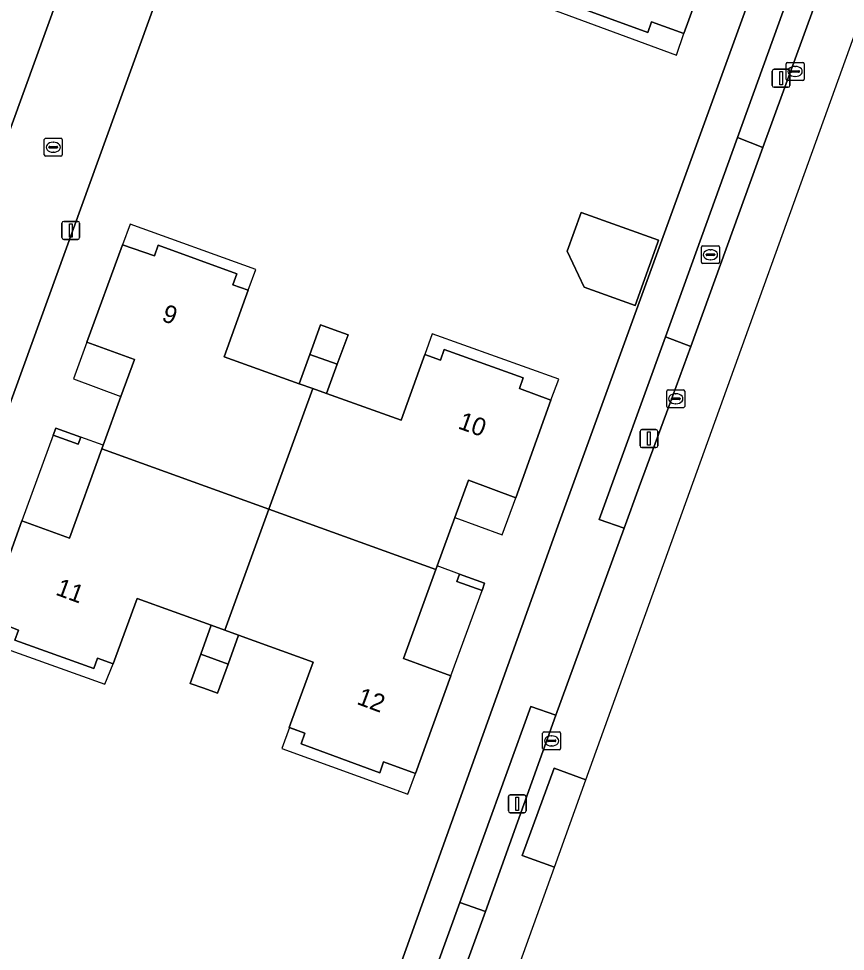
# Model space of a CAD drawing. Extents: x 155887 to 156869, y 383880 to 384678.
# Drawn here: x 156722.6 to 156768.8, y 384103.4 to 384155.6 of the extents above; entities that cross this region are included whole.
import ezdxf

# ---------------------------------------------------------------- set-up
doc = ezdxf.new("R2010")
doc.units = 0
for name, color, linetype in [('IMGEO_Erf', 7, 'Continuous'), ('IMGEO_Groenvoorziening', 7, 'Continuous'), ('IMGEO_Haag', 7, 'Continuous'), ('IMGEO_Kolk', 7, 'Continuous'), ('IMGEO_Lichtmast', 7, 'Continuous'), ('IMGEO_Pand', 7, 'Continuous'), ('IMGEO_Pand_nummerreeks', 7, 'Continuous'), ('IMGEO_Pand_overbouw', 7, 'Continuous'), ('IMGEO_Parkeervlak_open', 7, 'Continuous'), ('IMGEO_Rijbaan_lokaal_open', 7, 'Continuous'), ('IMGEO_Rioolput', 7, 'Continuous'), ('IMGEO_Voetpad_open', 7, 'Continuous')]:
    doc.layers.add(name, color=color, linetype=linetype)

msp = doc.modelspace()

# ---------------------------------------------------------------- linework, layer by layer
at = {"layer": 'IMGEO_Erf'}
for points in [[(156785.484, 384217.152), (156762.028, 384244.15), (156702.835, 384080.846), (156718.715, 384062.632)], [(156721.885, 384060.186), (156727.592, 384057.564), (156727.82, 384058.123), (156737.823, 384085.568), (156752.766, 384127.202), (156785.484, 384217.152)], [(156761.79, 384160.158), (156759.82, 384154.742), (156758.015, 384155.397), (156757.795, 384154.796), (156753.397, 384156.4)], [(156720.836, 384122.088), (156722.808, 384127.499), (156725.468, 384126.532), (156727.276, 384131.53), (156727.35, 384131.732), (156728.335, 384134.455), (156729.101, 384136.516), (156726.442, 384137.485), (156728.431, 384142.937), (156730.211, 384142.316), (156730.422, 384142.92), (156734.829, 384141.306), (156734.606, 384140.703), (156735.466, 384140.393), (156735.315, 384139.98), (156734.11, 384136.666), (156738.31, 384135.166), (156738.909, 384136.809), (156739.507, 384138.452), (156740.273, 384138.173), (156741.039, 384137.894), (156740.442, 384136.256), (156739.845, 384134.617), (156744.007, 384133.13), (156745.19, 384136.382), (156745.34, 384136.795), (156746.202, 384136.482), (156746.419, 384137.085), (156750.835, 384135.494), (156750.627, 384134.906), (156752.388, 384134.248), (156750.414, 384128.79), (156747.777, 384129.785), (156747.014, 384127.69), (156746.028, 384124.979), (156745.953, 384124.773), (156744.143, 384119.801), (156746.794, 384118.839), (156744.812, 384113.379), (156743.031, 384114.026), (156742.811, 384113.425), (156738.413, 384115.029), (156738.632, 384115.631), (156737.753, 384115.947), (156737.903, 384116.361), (156739.1, 384119.607), (156734.925, 384121.117), (156734.337, 384119.49), (156733.748, 384117.863), (156732.974, 384118.143), (156732.216, 384118.417), (156732.804, 384120.044), (156733.392, 384121.671), (156729.25, 384123.169), (156728.055, 384119.922), (156727.903, 384119.509), (156727.032, 384119.83), (156726.819, 384119.241), (156722.402, 384120.826)]]:
    msp.add_lwpolyline(points, dxfattribs=at)
for points in [[(156748.746, 384222.717), (156729.008, 384230.275), (156713.159, 384216.382), (156675.458, 384112.297), (156698.866, 384085.52), (156698.981, 384085.572)], [(156754.076, 384144.739), (156758.404, 384143.188), (156758.346, 384143.027), (156757.096, 384139.538), (156754.242, 384140.56), (156753.298, 384142.568)], [(156726.098, 384132.185), (156725.951, 384131.781), (156724.55, 384132.288), (156724.697, 384132.692)], [(156747.278, 384124.522), (156748.679, 384124.015), (156748.532, 384123.611), (156747.132, 384124.117)]]:
    msp.add_lwpolyline(points, close=True, dxfattribs=at)
at = {"layer": 'IMGEO_Groenvoorziening'}
for points in [[(156767.708, 384157.902), (156766.253, 384158.427), (156762.823, 384148.938), (156764.239, 384148.375)], [(156758.97, 384133.889), (156760.201, 384137.255), (156758.784, 384137.787), (156755.082, 384127.579), (156756.483, 384127.088), (156757.328, 384129.399)], [(156752.663, 384116.638), (156751.259, 384117.124), (156747.294, 384106.163), (156748.733, 384105.664)]]:
    msp.add_lwpolyline(points, close=True, dxfattribs=at)
at = {"layer": 'IMGEO_Haag'}
for points in [[(156764.239, 384148.375), (156767.708, 384157.902), (156766.253, 384158.427), (156762.823, 384148.938)], [(156757.328, 384129.399), (156758.97, 384133.889), (156760.201, 384137.255), (156758.784, 384137.787), (156755.082, 384127.579), (156756.483, 384127.088)], [(156748.733, 384105.664), (156752.663, 384116.638), (156751.259, 384117.124), (156747.294, 384106.163)]]:
    msp.add_lwpolyline(points, close=True, dxfattribs=at)
at = {"layer": 'IMGEO_Kolk'}
for p, q in [((156765.539, 384152.197), (156765.539, 384153.049)), ((156765.614, 384153.123), (156766.466, 384153.123)), ((156765.798, 384152.617), (156765.798, 384152.629)), ((156765.841, 384152.666), (156766.239, 384152.666)), ((156766.027, 384152.903), (156766.052, 384152.903)), ((156766.282, 384152.629), (156766.282, 384152.617)), ((156766.54, 384153.049), (156766.54, 384152.197)), ((156766.466, 384152.123), (156765.614, 384152.123)), ((156766.236, 384152.58), (156765.838, 384152.58)), ((156766.05, 384152.343), (156766.025, 384152.343)), ((156724.059, 384147.96), (156724.059, 384148.812)), ((156724.134, 384148.886), (156724.986, 384148.886)), ((156724.547, 384148.666), (156724.572, 384148.666)), ((156725.06, 384148.812), (156725.06, 384147.96)), ((156724.318, 384148.38), (156724.318, 384148.392)), ((156724.756, 384148.343), (156724.358, 384148.343)), ((156724.361, 384148.429), (156724.759, 384148.429)), ((156724.57, 384148.106), (156724.545, 384148.106)), ((156724.802, 384148.392), (156724.802, 384148.38)), ((156724.986, 384147.886), (156724.134, 384147.886)), ((156758.865, 384133.901), (156758.865, 384134.753)), ((156758.94, 384134.827), (156759.792, 384134.827)), ((156759.353, 384134.607), (156759.378, 384134.607)), ((156759.866, 384134.753), (156759.866, 384133.901)), ((156759.124, 384134.321), (156759.124, 384134.333)), ((156759.562, 384134.284), (156759.164, 384134.284)), ((156759.167, 384134.37), (156759.565, 384134.37)), ((156759.376, 384134.047), (156759.351, 384134.047)), ((156759.608, 384134.333), (156759.608, 384134.321)), ((156759.792, 384133.827), (156758.94, 384133.827)), ((156751.923, 384114.778), (156751.923, 384115.63)), ((156751.998, 384115.704), (156752.85, 384115.704)), ((156752.924, 384115.63), (156752.924, 384114.778)), ((156752.182, 384115.198), (156752.182, 384115.21)), ((156752.62, 384115.161), (156752.222, 384115.161)), ((156752.225, 384115.247), (156752.623, 384115.247)), ((156752.411, 384115.484), (156752.436, 384115.484)), ((156752.666, 384115.21), (156752.666, 384115.198)), ((156752.85, 384114.704), (156751.998, 384114.704)), ((156752.434, 384114.924), (156752.409, 384114.924))]:
    msp.add_line(p, q, dxfattribs=at)
for points in [[(156765.539, 384152.197), (156765.539, 384153.049)], [(156765.614, 384153.123), (156766.466, 384153.123)], [(156766.54, 384153.049), (156766.54, 384152.197)], [(156766.466, 384152.123), (156765.614, 384152.123)], [(156724.059, 384147.96), (156724.059, 384148.812)], [(156724.134, 384148.886), (156724.986, 384148.886)], [(156725.06, 384148.812), (156725.06, 384147.96)], [(156724.986, 384147.886), (156724.134, 384147.886)], [(156758.865, 384133.901), (156758.865, 384134.753)], [(156758.94, 384134.827), (156759.792, 384134.827)], [(156759.866, 384134.753), (156759.866, 384133.901)], [(156759.792, 384133.827), (156758.94, 384133.827)], [(156751.923, 384114.778), (156751.923, 384115.63)], [(156751.998, 384115.704), (156752.85, 384115.704)], [(156752.924, 384115.63), (156752.924, 384114.778)], [(156752.85, 384114.704), (156751.998, 384114.704)]]:
    msp.add_lwpolyline(points, dxfattribs=at)
for centre, radius, start, end in [((156765.616, 384153.047), 0.0765, 91.552, 178.448), ((156765.616, 384153.047), 0.0765, 91.552, 178.448), ((156765.838, 384152.626), 0.0403, 85.8775, 175.7526), ((156766.243, 384152.628), 0.0386, 1.7309, 96.639), ((156766.464, 384153.047), 0.0765, 1.552, 88.448), ((156766.464, 384153.047), 0.0765, 1.552, 88.448), ((156765.616, 384152.199), 0.0765, 181.552, 268.448), ((156765.616, 384152.199), 0.0765, 181.552, 268.448), ((156765.835, 384152.616), 0.0366, 178.938, 274.7102), ((156766.239, 384152.623), 0.043, 264.8664, 352.4533), ((156766.464, 384152.199), 0.0765, 271.552, 358.448), ((156766.464, 384152.199), 0.0765, 271.552, 358.448), ((156724.136, 384148.81), 0.0765, 91.552, 178.448), ((156724.136, 384148.81), 0.0765, 91.552, 178.448), ((156724.984, 384148.81), 0.0765, 1.552, 88.448), ((156724.984, 384148.81), 0.0765, 1.552, 88.448), ((156724.136, 384147.962), 0.0765, 181.552, 268.448), ((156724.136, 384147.962), 0.0765, 181.552, 268.448), ((156724.358, 384148.389), 0.0403, 85.8775, 175.7526), ((156724.355, 384148.379), 0.0366, 178.938, 274.7102), ((156724.759, 384148.386), 0.043, 264.8664, 352.4533), ((156724.763, 384148.391), 0.0386, 1.7309, 96.639), ((156724.984, 384147.962), 0.0765, 271.552, 358.448), ((156724.984, 384147.962), 0.0765, 271.552, 358.448), ((156758.942, 384134.751), 0.0765, 91.552, 178.448), ((156758.942, 384134.751), 0.0765, 91.552, 178.448), ((156759.79, 384134.751), 0.0765, 1.552, 88.448), ((156759.79, 384134.751), 0.0765, 1.552, 88.448), ((156758.942, 384133.903), 0.0765, 181.552, 268.448), ((156758.942, 384133.903), 0.0765, 181.552, 268.448), ((156759.164, 384134.33), 0.0403, 85.8775, 175.7526), ((156759.161, 384134.32), 0.0366, 178.938, 274.7102), ((156759.565, 384134.327), 0.043, 264.8664, 352.4533), ((156759.569, 384134.332), 0.0386, 1.7309, 96.639), ((156759.79, 384133.903), 0.0765, 271.552, 358.448), ((156759.79, 384133.903), 0.0765, 271.552, 358.448), ((156752, 384115.628), 0.0765, 91.552, 178.448), ((156752, 384115.628), 0.0765, 91.552, 178.448), ((156752.848, 384115.628), 0.0765, 1.552, 88.448), ((156752.848, 384115.628), 0.0765, 1.552, 88.448), ((156752.222, 384115.207), 0.0403, 85.8775, 175.7526), ((156752.219, 384115.197), 0.0366, 178.938, 274.7102), ((156752.623, 384115.204), 0.043, 264.8664, 352.4533), ((156752.627, 384115.209), 0.0386, 1.7309, 96.639), ((156752, 384114.78), 0.0765, 181.552, 268.448), ((156752, 384114.78), 0.0765, 181.552, 268.448), ((156752.848, 384114.78), 0.0765, 271.552, 358.448), ((156752.848, 384114.78), 0.0765, 271.552, 358.448)]:
    msp.add_arc(centre, radius, start, end, dxfattribs=at)
for centre, major_axis, ratio, start_param, end_param in [((156766.026, 384152.623), (-0.387, 0.002), 0.722429, 4.712389, 7.853982), ((156766.051, 384152.623), (-0.39, 0.002), 0.717154, 1.570796, 4.712389), ((156724.546, 384148.386), (-0.387, 0.002), 0.722429, 4.712389, 7.853982), ((156724.571, 384148.386), (-0.39, 0.002), 0.717154, 1.570796, 4.712389), ((156759.352, 384134.327), (-0.387, 0.002), 0.722429, 4.712389, 7.853982), ((156759.377, 384134.327), (-0.39, 0.002), 0.717154, 1.570796, 4.712389), ((156752.41, 384115.204), (-0.387, 0.002), 0.722429, 4.712389, 7.853982), ((156752.435, 384115.204), (-0.39, 0.002), 0.717154, 1.570796, 4.712389)]:
    msp.add_ellipse(centre, major_axis=major_axis, ratio=ratio, start_param=start_param, end_param=end_param, dxfattribs=at)
at = {"layer": 'IMGEO_Lichtmast'}
for p, q in [((156764.759, 384151.842), (156764.759, 384152.642)), ((156764.759, 384152.642), (156764.759, 384151.842)), ((156764.859, 384152.742), (156765.649, 384152.742)), ((156765.649, 384152.742), (156764.859, 384152.742)), ((156765.749, 384152.642), (156765.749, 384151.842)), ((156765.749, 384151.842), (156765.749, 384152.642)), ((156765.649, 384151.742), (156764.859, 384151.742)), ((156764.859, 384151.742), (156765.649, 384151.742)), ((156725.045, 384143.337), (156725.045, 384144.137)), ((156725.045, 384144.137), (156725.045, 384143.337)), ((156725.145, 384144.237), (156725.935, 384144.237)), ((156725.935, 384144.237), (156725.145, 384144.237)), ((156726.035, 384144.137), (156726.035, 384143.337)), ((156726.035, 384143.337), (156726.035, 384144.137)), ((156725.935, 384143.237), (156725.145, 384143.237)), ((156725.145, 384143.237), (156725.935, 384143.237)), ((156757.369, 384131.7), (156757.369, 384132.5)), ((156757.369, 384132.5), (156757.369, 384131.7)), ((156757.469, 384132.6), (156758.259, 384132.6)), ((156758.259, 384132.6), (156757.469, 384132.6)), ((156758.359, 384132.5), (156758.359, 384131.7)), ((156758.359, 384131.7), (156758.359, 384132.5)), ((156758.259, 384131.6), (156757.469, 384131.6)), ((156757.469, 384131.6), (156758.259, 384131.6)), ((156750.008, 384111.286), (156750.008, 384112.086)), ((156750.008, 384112.086), (156750.008, 384111.286)), ((156750.108, 384112.186), (156750.898, 384112.186)), ((156750.898, 384112.186), (156750.108, 384112.186)), ((156750.998, 384112.086), (156750.998, 384111.286)), ((156750.998, 384111.286), (156750.998, 384112.086)), ((156750.898, 384111.186), (156750.108, 384111.186)), ((156750.108, 384111.186), (156750.898, 384111.186))]:
    msp.add_line(p, q, dxfattribs=at)
for points in [[(156765.179, 384152.617), (156765.329, 384152.617), (156765.329, 384151.867), (156765.179, 384151.867), (156765.179, 384152.617)], [(156725.465, 384144.112), (156725.615, 384144.112), (156725.615, 384143.362), (156725.465, 384143.362), (156725.465, 384144.112)], [(156757.789, 384132.475), (156757.939, 384132.475), (156757.939, 384131.725), (156757.789, 384131.725), (156757.789, 384132.475)], [(156750.428, 384112.061), (156750.578, 384112.061), (156750.578, 384111.311), (156750.428, 384111.311), (156750.428, 384112.061)]]:
    msp.add_lwpolyline(points, dxfattribs=at)
for centre, start, end in [((156764.859, 384152.642), 90, 180), ((156764.859, 384152.642), 90, 180), ((156765.649, 384152.642), 0, 90), ((156765.649, 384152.642), 360, 90), ((156764.859, 384151.842), 180, 270), ((156764.859, 384151.842), 180, 270), ((156765.649, 384151.842), 270, 0), ((156765.649, 384151.842), 270, 0), ((156725.145, 384144.137), 90, 180), ((156725.145, 384144.137), 90, 180), ((156725.935, 384144.137), 0, 90), ((156725.935, 384144.137), 360, 90), ((156725.145, 384143.337), 180, 270), ((156725.145, 384143.337), 180, 270), ((156725.935, 384143.337), 270, 0), ((156725.935, 384143.337), 270, 0), ((156757.469, 384132.5), 90, 180), ((156757.469, 384132.5), 90, 180), ((156758.259, 384132.5), 0, 90), ((156758.259, 384132.5), 360, 90), ((156757.469, 384131.7), 180, 270), ((156757.469, 384131.7), 180, 270), ((156758.259, 384131.7), 270, 0), ((156758.259, 384131.7), 270, 0), ((156750.108, 384112.086), 90, 180), ((156750.108, 384112.086), 90, 180), ((156750.898, 384112.086), 0, 90), ((156750.898, 384112.086), 360, 90), ((156750.108, 384111.286), 180, 270), ((156750.108, 384111.286), 180, 270), ((156750.898, 384111.286), 270, 0), ((156750.898, 384111.286), 270, 0)]:
    msp.add_arc(centre, 0.1, start, end, dxfattribs=at)
at = {"layer": 'IMGEO_Pand'}
for points in [[(156761.79, 384160.158), (156759.14, 384161.122), (156760.957, 384166.122), (156751.602, 384169.514), (156749.143, 384162.765), (156749.909, 384162.488), (156754.084, 384160.978), (156752.887, 384157.732), (156752.737, 384157.318), (156753.616, 384157.002), (156753.397, 384156.4), (156757.795, 384154.796), (156758.015, 384155.397), (156759.82, 384154.742)], [(156754.242, 384140.56), (156757.096, 384139.538), (156758.346, 384143.027), (156758.404, 384143.188), (156754.076, 384144.739), (156753.298, 384142.568)], [(156735.315, 384139.98), (156735.466, 384140.393), (156734.606, 384140.703), (156734.829, 384141.306), (156730.422, 384142.92), (156730.211, 384142.316), (156728.431, 384142.937), (156726.442, 384137.485), (156729.101, 384136.516), (156728.335, 384134.455), (156727.35, 384131.732), (156727.276, 384131.53), (156736.62, 384128.149), (156739.077, 384134.892), (156738.31, 384135.166), (156734.11, 384136.666)], [(156741.039, 384137.894), (156740.273, 384138.173), (156739.507, 384138.452), (156738.909, 384136.809), (156740.442, 384136.256)], [(156752.388, 384134.248), (156750.627, 384134.906), (156750.835, 384135.494), (156746.419, 384137.085), (156746.202, 384136.482), (156745.34, 384136.795), (156745.19, 384136.382), (156744.007, 384133.13), (156739.845, 384134.617), (156739.077, 384134.892), (156736.62, 384128.149), (156745.953, 384124.773), (156746.028, 384124.979), (156747.014, 384127.69), (156747.777, 384129.785), (156750.414, 384128.79)], [(156740.442, 384136.256), (156738.909, 384136.809), (156738.31, 384135.166), (156739.077, 384134.892), (156739.845, 384134.617)], [(156724.697, 384132.692), (156724.55, 384132.288), (156725.951, 384131.781), (156726.098, 384132.185)], [(156729.25, 384123.169), (156733.392, 384121.671), (156734.159, 384121.394), (156736.62, 384128.149), (156727.276, 384131.53), (156725.468, 384126.532), (156722.808, 384127.499), (156720.836, 384122.088), (156722.606, 384121.393), (156722.402, 384120.826), (156726.819, 384119.241), (156727.032, 384119.83), (156727.903, 384119.509), (156728.055, 384119.922)], [(156746.794, 384118.839), (156744.143, 384119.801), (156745.953, 384124.773), (156736.62, 384128.149), (156734.159, 384121.394), (156734.925, 384121.117), (156739.1, 384119.607), (156737.903, 384116.361), (156737.753, 384115.947), (156738.632, 384115.631), (156738.413, 384115.029), (156742.811, 384113.425), (156743.031, 384114.026), (156744.812, 384113.379)], [(156747.278, 384124.522), (156747.132, 384124.117), (156748.532, 384123.611), (156748.679, 384124.015)], [(156734.925, 384121.117), (156734.159, 384121.394), (156733.392, 384121.671), (156732.804, 384120.044), (156734.337, 384119.49)], [(156734.337, 384119.49), (156732.804, 384120.044), (156732.216, 384118.417), (156732.974, 384118.143), (156733.748, 384117.863)]]:
    msp.add_lwpolyline(points, close=True, dxfattribs=at)
at = {"layer": 'IMGEO_Pand_overbouw'}
for points in [[(156759.82, 384154.742), (156758.015, 384155.397), (156757.795, 384154.796), (156753.397, 384156.4), (156753.616, 384157.002), (156752.753, 384157.312), (156752.327, 384156.14), (156759.404, 384153.536)], [(156728.431, 384142.937), (156730.211, 384142.316), (156730.422, 384142.92), (156734.829, 384141.306), (156734.606, 384140.703), (156735.466, 384140.393), (156735.882, 384141.56), (156728.856, 384144.09)], [(156752.388, 384134.248), (156752.819, 384135.427), (156745.754, 384137.959), (156745.34, 384136.795), (156746.202, 384136.482), (156746.419, 384137.085), (156750.835, 384135.494), (156750.627, 384134.906)], [(156726.442, 384137.485), (156725.682, 384135.441), (156728.335, 384134.455), (156729.101, 384136.516)], [(156726.098, 384132.185), (156725.951, 384131.781), (156724.55, 384132.288), (156722.808, 384127.499), (156725.468, 384126.532), (156727.276, 384131.53), (156727.35, 384131.732)], [(156750.414, 384128.79), (156747.777, 384129.785), (156747.014, 384127.69), (156749.663, 384126.726)], [(156748.532, 384123.611), (156747.132, 384124.117), (156747.278, 384124.522), (156746.028, 384124.979), (156745.953, 384124.773), (156744.143, 384119.801), (156746.794, 384118.839)], [(156720.836, 384122.088), (156720.395, 384120.89), (156727.449, 384118.365), (156727.903, 384119.509), (156727.032, 384119.83), (156726.819, 384119.241), (156722.402, 384120.826), (156722.606, 384121.393)], [(156744.812, 384113.379), (156743.031, 384114.026), (156742.811, 384113.425), (156738.413, 384115.029), (156738.632, 384115.631), (156737.769, 384115.941), (156737.343, 384114.769), (156744.39, 384112.215)]]:
    msp.add_lwpolyline(points, close=True, dxfattribs=at)
at = {"layer": 'IMGEO_Parkeervlak_open'}
for points in [[(156764.239, 384148.375), (156762.823, 384148.938), (156758.784, 384137.787), (156760.201, 384137.255)], [(156748.733, 384105.664), (156747.294, 384106.163), (156743.385, 384095.374), (156744.807, 384094.917)]]:
    msp.add_lwpolyline(points, close=True, dxfattribs=at)
at = {"layer": 'IMGEO_Rijbaan_lokaal_open'}
for points in [[(156760.882, 384256.094), (156758.942, 384250.73), (156758.21, 384248.7), (156748.746, 384222.717), (156698.981, 384085.572), (156698.866, 384085.52), (156696.881, 384084.965), (156696.693, 384084.921), (156691.649, 384084.815), (156701.762, 384073.232), (156702.148, 384078.82), (156702.835, 384080.846), (156762.028, 384244.15)], [(156731.499, 384049.697), (156752.581, 384108.142), (156750.776, 384108.802), (156752.564, 384113.686), (156754.346, 384113.034), (156774.9, 384170.016), (156773.225, 384170.619), (156775.002, 384175.506), (156776.667, 384174.913), (156796.393, 384229.598)], [(156767.708, 384157.902), (156764.239, 384148.375), (156760.201, 384137.255), (156758.97, 384133.889), (156757.328, 384129.399), (156756.483, 384127.088), (156752.663, 384116.638), (156748.733, 384105.664), (156744.807, 384094.917), (156741.379, 384085.434), (156737.803, 384075.261), (156733, 384062.216), (156730.967, 384056.67), (156730.215, 384054.611), (156730.676, 384054.408), (156730.57, 384054.248)]]:
    msp.add_lwpolyline(points, dxfattribs=at)
msp.add_lwpolyline([(156752.581, 384108.142), (156754.346, 384113.034), (156752.564, 384113.686), (156750.776, 384108.802)], close=True, dxfattribs=at)
at = {"layer": 'IMGEO_Rioolput'}
for p, q in [((156760.805, 384141.953), (156760.805, 384142.805)), ((156760.88, 384142.879), (156761.732, 384142.879)), ((156761.806, 384142.805), (156761.806, 384141.953)), ((156761.064, 384142.373), (156761.064, 384142.385)), ((156761.502, 384142.336), (156761.104, 384142.336)), ((156761.107, 384142.422), (156761.505, 384142.422)), ((156761.293, 384142.659), (156761.318, 384142.659)), ((156761.548, 384142.385), (156761.548, 384142.373)), ((156761.732, 384141.879), (156760.88, 384141.879)), ((156761.316, 384142.099), (156761.291, 384142.099))]:
    msp.add_line(p, q, dxfattribs=at)
for points in [[(156760.805, 384141.953), (156760.805, 384142.805)], [(156760.88, 384142.879), (156761.732, 384142.879)], [(156761.806, 384142.805), (156761.806, 384141.953)], [(156761.732, 384141.879), (156760.88, 384141.879)]]:
    msp.add_lwpolyline(points, dxfattribs=at)
for centre, radius, start, end in [((156760.882, 384142.803), 0.0765, 91.552, 178.448), ((156760.882, 384142.803), 0.0765, 91.552, 178.448), ((156761.73, 384142.803), 0.0765, 1.552, 88.448), ((156761.73, 384142.803), 0.0765, 1.552, 88.448), ((156761.104, 384142.382), 0.0403, 85.8775, 175.7526), ((156761.101, 384142.372), 0.0366, 178.938, 274.7102), ((156761.505, 384142.379), 0.043, 264.8664, 352.4533), ((156761.509, 384142.384), 0.0386, 1.7309, 96.639), ((156760.882, 384141.955), 0.0765, 181.552, 268.448), ((156760.882, 384141.955), 0.0765, 181.552, 268.448), ((156761.73, 384141.955), 0.0765, 271.552, 358.448), ((156761.73, 384141.955), 0.0765, 271.552, 358.448)]:
    msp.add_arc(centre, radius, start, end, dxfattribs=at)
for centre, major_axis, ratio, start_param, end_param in [((156761.292, 384142.379), (-0.387, 0.002), 0.722429, 4.712389, 7.853982), ((156761.317, 384142.379), (-0.39, 0.002), 0.717154, 1.570796, 4.712389)]:
    msp.add_ellipse(centre, major_axis=major_axis, ratio=ratio, start_param=start_param, end_param=end_param, dxfattribs=at)
at = {"layer": 'IMGEO_Voetpad_open'}
for points in [[(156813.189, 384294.055), (156806.307, 384274.964), (156788.246, 384224.829), (156786.203, 384219.126), (156785.484, 384217.152), (156752.766, 384127.202), (156737.823, 384085.568), (156727.82, 384058.123), (156727.592, 384057.564), (156726.657, 384054.995), (156725.048, 384050.605)], [(156730.57, 384054.248), (156730.676, 384054.408), (156730.215, 384054.611), (156730.967, 384056.67), (156729.446, 384057.212), (156731.493, 384062.784), (156736.295, 384075.828), (156737.803, 384075.261), (156741.379, 384085.434), (156739.944, 384085.957), (156743.385, 384095.374), (156747.294, 384106.163), (156751.259, 384117.124), (156752.663, 384116.638), (156756.483, 384127.088), (156755.082, 384127.579), (156758.784, 384137.787), (156762.823, 384148.938), (156766.253, 384158.427)]]:
    msp.add_lwpolyline(points, dxfattribs=at)

# ---------------------------------------------------------------- texts
at = {"layer": 'IMGEO_Pand_nummerreeks'}
for s, rotation, p in [('9', 340.3877, (156730.569, 384138.695)), ('10', 340.3877, (156747.136, 384132.682)), ('11', 339.8204, (156724.638, 384123.386)), ('12', 339.6485, (156741.476, 384117.278))]:
    msp.add_text(s, height=1, rotation=rotation, dxfattribs=at).set_placement(p)

doc.saveas('drawing.dxf')
